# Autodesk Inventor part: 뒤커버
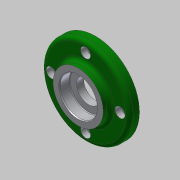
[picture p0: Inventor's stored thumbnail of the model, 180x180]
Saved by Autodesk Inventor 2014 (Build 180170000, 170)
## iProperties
Created: 2019-01
Part Number: 뒤커버
Material: 알루미늄 6061
Document SubType Name: Modeling
Designer: mduedu
Density: 1 g/cm^3
Appearance: 알루미늄 - 평지
Author: mduedu
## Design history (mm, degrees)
sketch "스케치1"
  geometry: L1 (0, 0)-(6, 0); L2 (6, 0)-(6, 20); L3 (6, 20)-(0, 20); L4 (0, 20)-(0, 0); L5 (6, 0)-(14, 0); L6 (14, 0)-(14, 35); L7 (14, 35)-(6, 35); L8 (6, 35)-(6, 0); L9 (14, 0)-(19, 0); L10 (19, 0)-(19, 20); L11 (19, 20)-(14, 20); L12 (14, 20)-(14, 0)
  constraints: 24 end point, 6 parallel, 3 horizontal, 3 perpendicular
  dimensions: "d6" = 70 diameter of L7 L5; "d8" = 40 diameter of L3 L1; "d9" = 40 diameter of L11 L9; "d10" = 5 distance of L10.end L11.end; "d11" = 6 distance of L2.end L3.end; "d12" = 19 distance between parallel lines of L4 L10; "d13" = 8 distance of L6.end L7.end (derived)
revolve "회전1" sketch "스케치1" stored, may be unused: angle "d5" = 90 deg
sketch "스케치2" dims "d14" = 55
  geometry: 7 further points
  constraints: 2 coincident, 2 vertical alignment, 7 other
  dimensions: "d17" = 360 deg dimension on point (0, 0) point (0, 27.5) (derived)
sketch "스케치3"
  geometry: 4 further points
  constraints: 4 other
hole "구멍1" sketch "스케치3" at (0, 27.5), (-27.5, 0), (27.5, 0), (0, -27.5) diameter "d19" = 4.5; stored, may be unused: countersink angle "d23" = 90 deg, drill point angle "d25" = 0 deg; dims "d20" = 6, "d21" = 8, "d22" = 4.6, "d24" = 8
fillet "모깎기1" dims "d26" = 3
sketch "스케치4"
  geometry: C1 r 9.5 at (0, 0); 1 further point
  constraints: 1 centre point, 1 coincident
  dimensions: "d27" = 19 diameter of C1
extrude "돌출1" cut sketch "스케치4" stored distance "d28" = 10; taper "d29" = 0 deg
sketch "스케치5"
  geometry: C1 r 15 at (0, 0); 1 further point
  constraints: 1 centre point, 1 coincident
  dimensions: "d31" = 30 diameter of C1
extrude "돌출2" cut sketch "스케치5" distance "d32" = 8.3; taper "d33" = 0 deg
chamfer "모따기1" distance "d34" = 0.8; stored, may be unused: second distance "d35" = 2, angle "d36" = 30 deg
fillet "모깎기2" dims "d37" = 3
fillet "모깎기3" dims "d38" = 0.5
sketch "스케치6"
  geometry: C1 r 16.5 at (0, 0); 1 further point
  constraints: 1 centre point, 1 coincident
  dimensions: "d39" = 33 diameter of C1
extrude "돌출3" cut sketch "스케치6" distance "d40" = 5; taper "d41" = 0 deg
fillet "모깎기4" dims "d42" = 3
chamfer "모따기2" distance "d43" = 1; stored, may be unused: second distance "d44" = 2, angle "d45" = 30 deg
node "솔리드1"
